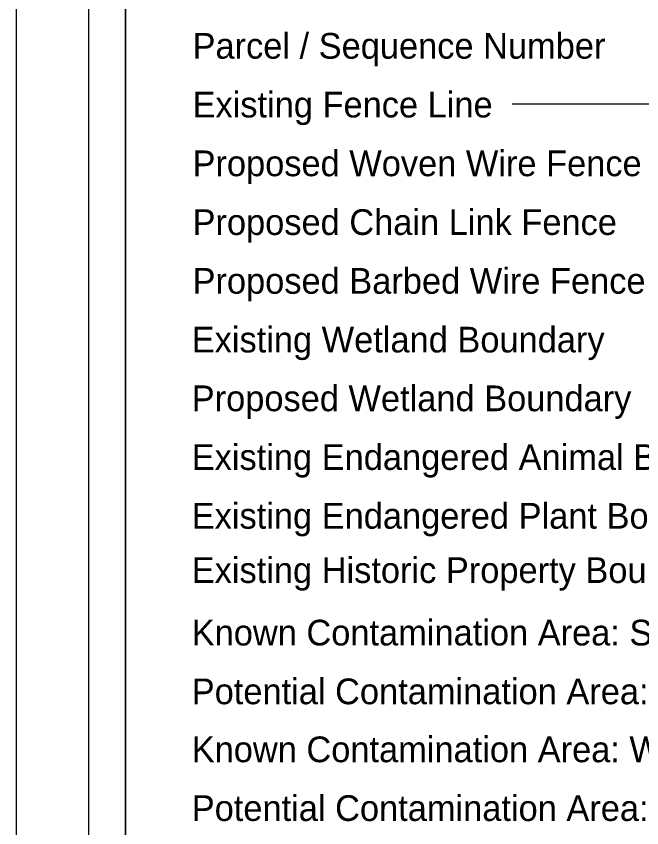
# Model space of a CAD drawing. Extents: x 811508 to 813252, y 647626 to 648754.
# Drawn here: x 811508.1 to 811728.4, y 648182.1 to 648468 of the extents above; entities that cross this region are included whole.
import ezdxf

# ---------------------------------------------------------------- set-up
doc = ezdxf.new("R2010")
doc.units = 0
for name, color, linetype in [('Sheet Cutting Line CELL', 7, 'Continuous'), ('Sheet Plot Border Inside CELL', 7, 'Continuous'), ('Sheet Plot Border Outside CELL', 7, 'Continuous'), ('Sheet_Plan', 7, 'Continuous'), ('Sheet_Symbology', 7, 'Continuous'), ('z - Construction', 7, 'Continuous')]:
    doc.layers.add(name, color=color, linetype=linetype)

msp = doc.modelspace()

# ---------------------------------------------------------------- linework, layer by layer
at = {"layer": 'Sheet Cutting Line CELL'}
msp.add_line((811533.6, 648737.99), (811533.6, 647637.99), dxfattribs=at)
at = {"layer": 'Sheet Plot Border Inside CELL'}
msp.add_lwpolyline([(811546.6, 647660.44), (813213.1, 647660.44), (813213.1, 648715.54), (811546.6, 648715.54)], close=True, dxfattribs=at)
at = {"layer": 'Sheet Plot Border Outside CELL'}
msp.add_lwpolyline([(811533.6, 647637.99), (813217.6, 647637.99), (813217.6, 648737.99), (811533.6, 648737.99)], close=True, dxfattribs=at)
at = {"layer": 'Sheet_Plan'}
msp.add_line((811546.61, 647664.09), (811546.6, 648715.54), dxfattribs=at)
at = {"layer": 'Sheet_Symbology'}
msp.add_line((811832.99, 648437.08), (811682.8, 648437.08), dxfattribs=at)
at = {"layer": 'z - Construction'}
msp.add_line((811508.14, 648754), (811508.14, 647625.63), dxfattribs=at)

# ---------------------------------------------------------------- texts
at = {"layer": 'Sheet_Symbology'}
for s, p in [('Parcel / Sequence Number', (811570.23, 648453.08)), ('Existing Fence Line', (811570.23, 648432.38)), ('Proposed Woven Wire Fence', (811570.23, 648411.68)), ('Proposed Chain Link Fence', (811570.23, 648390.98)), ('Proposed Barbed Wire Fence', (811570.23, 648370.28)), ('Existing Wetland Boundary', (811569.94, 648349.59)), ('Proposed Wetland Boundary', (811569.94, 648328.89)), ('Existing Endangered Animal Boundary', (811569.94, 648308.2)), ('Existing Endangered Plant Boundary', (811569.94, 648287.5)), ('Existing Historic Property Boundary', (811569.94, 648268.38)), ('Known Contamination Area: Soil', (811569.94, 648246.36)), ('Potential Contamination Area: Soil', (811569.94, 648225.66)), ('Known Contamination Area: Water', (811569.94, 648205.23)), ('Potential Contamination Area: Water', (811569.94, 648184.53))]:
    msp.add_text(s, height=9.056, dxfattribs=at).set_placement(p)

doc.saveas('drawing.dxf')
